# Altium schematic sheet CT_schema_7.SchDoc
size 226 x 144 mm
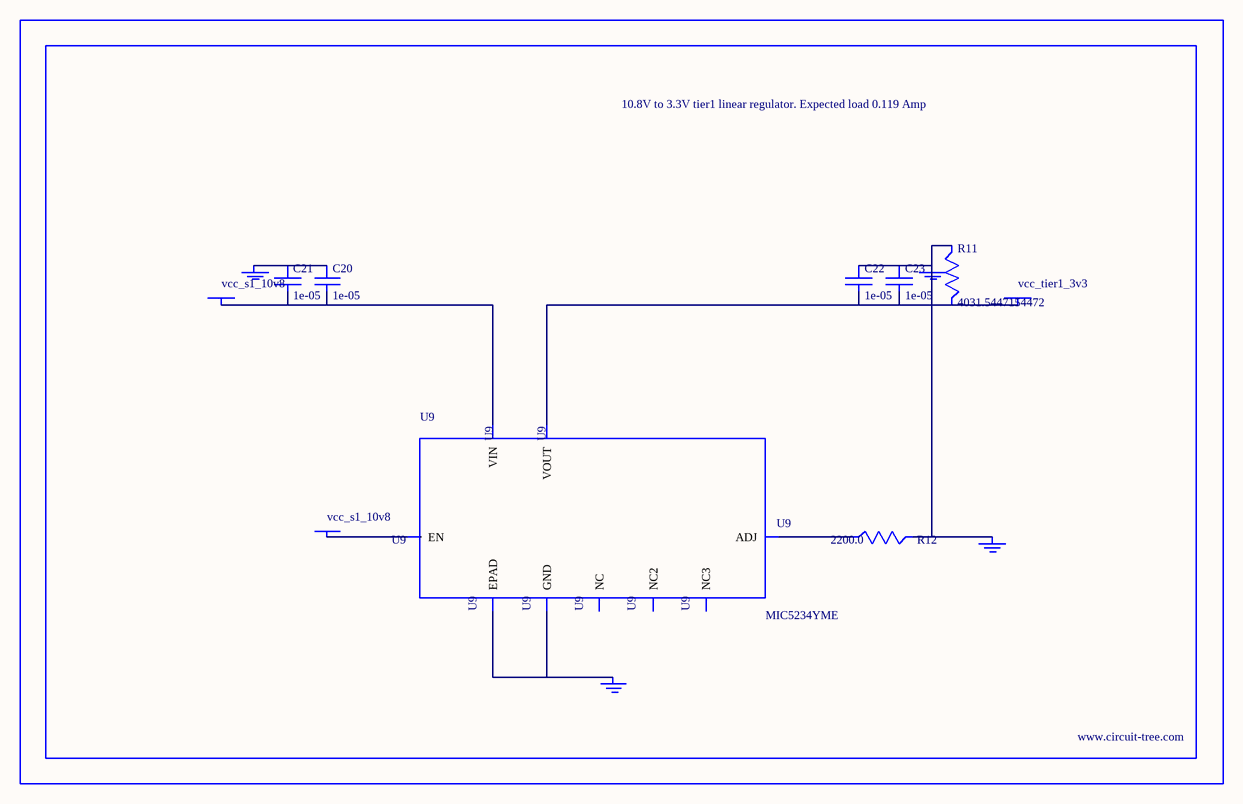
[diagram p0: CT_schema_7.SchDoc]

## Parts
BORDER6  (no value)
C20  1e-05  [C1210]
C21  1e-05  [C1210]
C22  1e-05  [C1210]
C23  1e-05  [C1210]
GND_INSTANCE_6_0  (no value)
GND_INSTANCE_6_1  (no value)
GND_INSTANCE_6_2  (no value)
GND_INSTANCE_6_3  (no value)
POWER_INSTANCE_6_0  vcc_tier1_3v3
POWER_INSTANCE_6_1  vcc_s1_10v8
POWER_INSTANCE_6_2  vcc_s1_10v8
R11  4031.5447154472  [R0603]
R12  2200.0  [R0603]
U9  MIC5234YME  [SOIC-8_EP]

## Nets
NetC20_1: C20.1 C21.1 GND_INSTANCE_6_3.0(GND)
NetC20_2: C20.2 C21.2 POWER_INSTANCE_6_2.0(PWR) U9.8(VIN)
NetC22_1: C22.1 C23.1 GND_INSTANCE_6_0.0(GND) GND_INSTANCE_6_1.0(GND) R11.1 R12.2
NetC22_2: C22.2 C23.2 POWER_INSTANCE_6_0.0(PWR) R11.2 U9.1(VOUT)
NetGND_INSTANCE_6_2_0: GND_INSTANCE_6_2.0(GND) U9.7(GND) U9.EPAD
NetPOWER_INSTANCE_6_1_0: POWER_INSTANCE_6_1.0(PWR) U9.5(EN)
NetR12_1: R12.1 U9.4(ADJ)

Not connected (* = marked no-connect by the designer): U9 2(NC) 3(NC2) 6(NC3)

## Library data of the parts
BORDER6 = BORDER_PAGE6
C20-C23 = C1210C106K5PACTU
GND_INSTANCE_6_0-GND_INSTANCE_6_3 = GND
POWER_INSTANCE_6_0-POWER_INSTANCE_6_2 = PWR
R11 = R11
R12 = RC0603JR-072K2L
